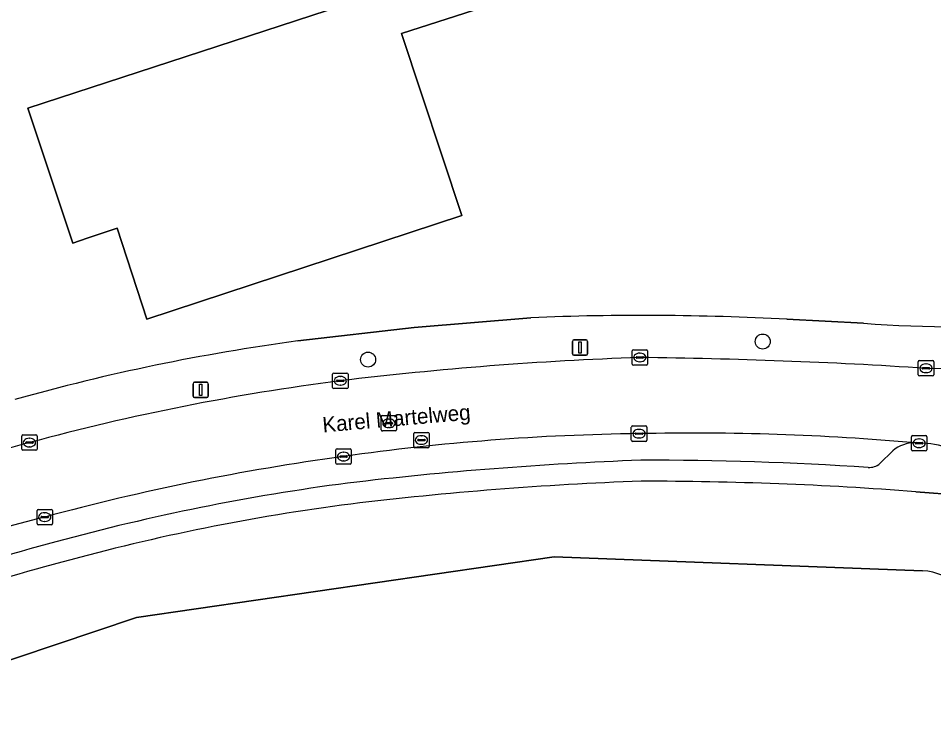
# Model space of a CAD drawing. Extents: x 159499 to 160349, y 382524 to 383273.
# Drawn here: x 159656.9 to 159716.4, y 382705.2 to 382752 of the extents above; entities that cross this region are included whole.
import ezdxf

# ---------------------------------------------------------------- set-up
doc = ezdxf.new("R2010")
doc.units = 0
for name, color, linetype in [('IMGEO_Boom', 7, 'Continuous'), ('IMGEO_Erf', 7, 'Continuous'), ('IMGEO_Kolk', 7, 'Continuous'), ('IMGEO_Lichtmast', 7, 'Continuous'), ('IMGEO_Openbare_ruimte_label', 7, 'Continuous'), ('IMGEO_Pand', 7, 'Continuous'), ('IMGEO_Parkeervlak_open', 7, 'Continuous'), ('IMGEO_Rijbaan_lokaal_open', 7, 'Continuous'), ('IMGEO_Rioolput', 7, 'Continuous'), ('IMGEO_Voetpad_open', 7, 'Continuous')]:
    doc.layers.add(name, color=color, linetype=linetype)

msp = doc.modelspace()

# ---------------------------------------------------------------- linework, layer by layer
at = {"layer": 'IMGEO_Boom'}
for centre in [(159705.309, 382730.985), (159679.639, 382729.808)]:
    msp.add_circle(centre, 0.489, dxfattribs=at)
at = {"layer": 'IMGEO_Erf'}
msp.add_lwpolyline([(159687.697, 382752.922), (159681.815, 382751.023), (159685.741, 382739.181), (159665.238, 382732.431), (159663.316, 382738.364), (159661.358, 382737.709), (159660.423, 382737.392), (159657.503, 382746.17), (159678.029, 382752.88), (159676.106, 382758.788), (159667.31, 382755.914), (159665.398, 382761.756), (159668.349, 382762.731), (159667.364, 382765.67), (159664.417, 382764.699), (159662.523, 382770.552), (159671.303, 382773.418), (159672.267, 382770.481), (159675.209, 382771.449), (159676.161, 382768.5), (159682.02, 382770.428), (159684.881, 382761.646)], close=True, dxfattribs=at)
for points in [[(159675.074, 382731.025), (159682.644, 382731.888), (159690.236, 382732.536)], [(159706.889, 382732.435), (159711.86, 382732.171)], [(159721.046, 382720.774), (159715.272, 382721.211)], [(159641.27, 382705.207), (159664.57, 382713.021), (159691.74, 382716.986), (159715.697, 382716.063)]]:
    msp.add_lwpolyline(points, dxfattribs=at)
for centre, radius, start, end in [((159697.488, 382555.269), 177.415, 86.96245, 92.34256), ((159718.869, 382831.635), 99.71, 265.96939, 273.05408), ((159693.42, 382596.018), 136.248, 97.73847, 105.65117), ((159705.287, 382500.203), 221.831, 92.03487, 96.93268), ((159697.556, 382491.794), 230.1, 85.58418, 90.03625), ((159696.201, 382584.04), 137.515, 97.39088, 105.38605), ((159693.098, 382590.157), 130.801, 104.78647, 112.89281), ((159715.545, 382712.325), 3.741, 45.57907, 87.6653)]:
    msp.add_arc(centre, radius, start, end, dxfattribs=at)
at = {"layer": 'IMGEO_Kolk'}
for p, q in [((159696.822, 382729.522), (159696.822, 382730.374)), ((159696.897, 382730.448), (159697.749, 382730.448)), ((159697.081, 382729.942), (159697.081, 382729.954)), ((159697.519, 382729.905), (159697.121, 382729.905)), ((159697.124, 382729.991), (159697.522, 382729.991)), ((159697.31, 382730.228), (159697.335, 382730.228)), ((159697.565, 382729.954), (159697.565, 382729.942)), ((159697.823, 382730.374), (159697.823, 382729.522)), ((159697.749, 382729.448), (159696.897, 382729.448)), ((159697.333, 382729.668), (159697.308, 382729.668)), ((159715.43, 382728.818), (159715.43, 382729.67)), ((159715.505, 382729.744), (159716.357, 382729.744)), ((159715.918, 382729.524), (159715.943, 382729.524)), ((159716.431, 382729.67), (159716.431, 382728.818)), ((159677.332, 382728.004), (159677.332, 382728.856)), ((159677.407, 382728.93), (159678.259, 382728.93)), ((159677.82, 382728.71), (159677.845, 382728.71)), ((159678.333, 382728.856), (159678.333, 382728.004)), ((159716.357, 382728.744), (159715.505, 382728.744)), ((159715.689, 382729.238), (159715.689, 382729.25)), ((159716.127, 382729.201), (159715.729, 382729.201)), ((159715.732, 382729.287), (159716.13, 382729.287)), ((159715.941, 382728.964), (159715.916, 382728.964)), ((159716.173, 382729.25), (159716.173, 382729.238)), ((159677.591, 382728.424), (159677.591, 382728.436)), ((159678.029, 382728.387), (159677.631, 382728.387)), ((159677.634, 382728.473), (159678.032, 382728.473)), ((159677.843, 382728.15), (159677.818, 382728.15)), ((159678.075, 382728.436), (159678.075, 382728.424)), ((159678.259, 382727.93), (159677.407, 382727.93)), ((159696.763, 382724.564), (159696.763, 382725.416)), ((159696.838, 382725.49), (159697.69, 382725.49)), ((159697.251, 382725.27), (159697.276, 382725.27)), ((159697.764, 382725.416), (159697.764, 382724.564)), ((159657.109, 382723.984), (159657.109, 382724.836)), ((159657.184, 382724.91), (159658.036, 382724.91)), ((159657.597, 382724.69), (159657.622, 382724.69)), ((159658.11, 382724.836), (159658.11, 382723.984)), ((159697.022, 382724.984), (159697.022, 382724.996)), ((159697.46, 382724.947), (159697.062, 382724.947)), ((159697.065, 382725.033), (159697.463, 382725.033)), ((159697.274, 382724.71), (159697.249, 382724.71)), ((159697.506, 382724.996), (159697.506, 382724.984)), ((159714.98, 382723.942), (159714.98, 382724.794)), ((159715.055, 382724.868), (159715.907, 382724.868)), ((159715.468, 382724.648), (159715.493, 382724.648)), ((159715.981, 382724.794), (159715.981, 382723.942)), ((159657.368, 382724.404), (159657.368, 382724.416)), ((159657.806, 382724.367), (159657.408, 382724.367)), ((159657.411, 382724.453), (159657.809, 382724.453)), ((159657.62, 382724.13), (159657.595, 382724.13)), ((159657.852, 382724.416), (159657.852, 382724.404)), ((159677.619, 382724.002), (159678.471, 382724.002)), ((159697.69, 382724.49), (159696.838, 382724.49)), ((159715.239, 382724.362), (159715.239, 382724.374)), ((159715.677, 382724.325), (159715.279, 382724.325)), ((159715.282, 382724.411), (159715.68, 382724.411)), ((159715.491, 382724.088), (159715.466, 382724.088)), ((159715.723, 382724.374), (159715.723, 382724.362)), ((159658.036, 382723.91), (159657.184, 382723.91)), ((159677.544, 382723.076), (159677.544, 382723.928)), ((159677.803, 382723.496), (159677.803, 382723.508)), ((159678.241, 382723.459), (159677.843, 382723.459)), ((159677.846, 382723.545), (159678.244, 382723.545)), ((159678.032, 382723.782), (159678.057, 382723.782)), ((159678.287, 382723.508), (159678.287, 382723.496)), ((159678.545, 382723.928), (159678.545, 382723.076)), ((159715.907, 382723.868), (159715.055, 382723.868)), ((159678.471, 382723.002), (159677.619, 382723.002)), ((159678.055, 382723.222), (159678.03, 382723.222)), ((159658.106, 382719.138), (159658.106, 382719.99)), ((159658.181, 382720.064), (159659.033, 382720.064)), ((159658.594, 382719.844), (159658.619, 382719.844)), ((159659.107, 382719.99), (159659.107, 382719.138)), ((159658.365, 382719.558), (159658.365, 382719.57)), ((159658.803, 382719.521), (159658.405, 382719.521)), ((159658.408, 382719.607), (159658.806, 382719.607)), ((159658.617, 382719.284), (159658.592, 382719.284)), ((159658.849, 382719.57), (159658.849, 382719.558)), ((159659.033, 382719.064), (159658.181, 382719.064))]:
    msp.add_line(p, q, dxfattribs=at)
for points in [[(159696.822, 382729.522), (159696.822, 382730.374)], [(159696.897, 382730.448), (159697.749, 382730.448)], [(159697.823, 382730.374), (159697.823, 382729.522)], [(159697.749, 382729.448), (159696.897, 382729.448)], [(159715.43, 382728.818), (159715.43, 382729.67)], [(159715.505, 382729.744), (159716.357, 382729.744)], [(159716.431, 382729.67), (159716.431, 382728.818)], [(159677.332, 382728.004), (159677.332, 382728.856)], [(159677.407, 382728.93), (159678.259, 382728.93)], [(159678.333, 382728.856), (159678.333, 382728.004)], [(159716.357, 382728.744), (159715.505, 382728.744)], [(159678.259, 382727.93), (159677.407, 382727.93)], [(159696.763, 382724.564), (159696.763, 382725.416)], [(159696.838, 382725.49), (159697.69, 382725.49)], [(159697.764, 382725.416), (159697.764, 382724.564)], [(159657.109, 382723.984), (159657.109, 382724.836)], [(159657.184, 382724.91), (159658.036, 382724.91)], [(159658.11, 382724.836), (159658.11, 382723.984)], [(159714.98, 382723.942), (159714.98, 382724.794)], [(159715.055, 382724.868), (159715.907, 382724.868)], [(159715.981, 382724.794), (159715.981, 382723.942)], [(159677.619, 382724.002), (159678.471, 382724.002)], [(159697.69, 382724.49), (159696.838, 382724.49)], [(159658.036, 382723.91), (159657.184, 382723.91)], [(159677.544, 382723.076), (159677.544, 382723.928)], [(159678.545, 382723.928), (159678.545, 382723.076)], [(159715.907, 382723.868), (159715.055, 382723.868)], [(159678.471, 382723.002), (159677.619, 382723.002)], [(159658.106, 382719.138), (159658.106, 382719.99)], [(159658.181, 382720.064), (159659.033, 382720.064)], [(159659.107, 382719.99), (159659.107, 382719.138)], [(159659.033, 382719.064), (159658.181, 382719.064)]]:
    msp.add_lwpolyline(points, dxfattribs=at)
for centre, radius, start, end in [((159696.899, 382730.372), 0.0765, 91.55205, 178.44795), ((159696.899, 382730.372), 0.0765, 91.55205, 178.44795), ((159697.121, 382729.951), 0.0403, 85.87752, 175.75265), ((159697.118, 382729.941), 0.0366, 178.93798, 274.71019), ((159697.522, 382729.948), 0.043, 264.86636, 352.45326), ((159697.526, 382729.953), 0.0386, 1.73085, 96.63898), ((159697.747, 382730.372), 0.0765, 1.55205, 88.44795), ((159697.747, 382730.372), 0.0765, 1.55205, 88.44795), ((159696.899, 382729.524), 0.0765, 181.55205, 268.44795), ((159696.899, 382729.524), 0.0765, 181.55205, 268.44795), ((159697.747, 382729.524), 0.0765, 271.55205, 358.44795), ((159697.747, 382729.524), 0.0765, 271.55205, 358.44795), ((159715.507, 382729.668), 0.0765, 91.55205, 178.44795), ((159715.507, 382729.668), 0.0765, 91.55205, 178.44795), ((159716.355, 382729.668), 0.0765, 1.55205, 88.44795), ((159716.355, 382729.668), 0.0765, 1.55205, 88.44795), ((159677.409, 382728.854), 0.0765, 91.55205, 178.44795), ((159677.409, 382728.854), 0.0765, 91.55205, 178.44795), ((159678.257, 382728.854), 0.0765, 1.55205, 88.44795), ((159678.257, 382728.854), 0.0765, 1.55205, 88.44795), ((159715.507, 382728.82), 0.0765, 181.55205, 268.44795), ((159715.507, 382728.82), 0.0765, 181.55205, 268.44795), ((159715.729, 382729.247), 0.0403, 85.87752, 175.75265), ((159715.726, 382729.237), 0.0366, 178.93798, 274.71019), ((159716.13, 382729.244), 0.043, 264.86636, 352.45326), ((159716.134, 382729.249), 0.0386, 1.73085, 96.63898), ((159716.355, 382728.82), 0.0765, 271.55205, 358.44795), ((159716.355, 382728.82), 0.0765, 271.55205, 358.44795), ((159677.631, 382728.433), 0.0403, 85.87752, 175.75265), ((159677.628, 382728.423), 0.0366, 178.93798, 274.71019), ((159678.032, 382728.43), 0.043, 264.86636, 352.45326), ((159678.036, 382728.435), 0.0386, 1.73085, 96.63898), ((159677.409, 382728.006), 0.0765, 181.55205, 268.44795), ((159677.409, 382728.006), 0.0765, 181.55205, 268.44795), ((159678.257, 382728.006), 0.0765, 271.55205, 358.44795), ((159678.257, 382728.006), 0.0765, 271.55205, 358.44795), ((159696.84, 382725.414), 0.0765, 91.55205, 178.44795), ((159696.84, 382725.414), 0.0765, 91.55205, 178.44795), ((159697.688, 382725.414), 0.0765, 1.55205, 88.44795), ((159697.688, 382725.414), 0.0765, 1.55205, 88.44795), ((159657.186, 382724.834), 0.0765, 91.55205, 178.44795), ((159657.186, 382724.834), 0.0765, 91.55205, 178.44795), ((159658.034, 382724.834), 0.0765, 1.55205, 88.44795), ((159658.034, 382724.834), 0.0765, 1.55205, 88.44795), ((159696.84, 382724.566), 0.0765, 181.55205, 268.44795), ((159696.84, 382724.566), 0.0765, 181.55205, 268.44795), ((159697.062, 382724.993), 0.0403, 85.87752, 175.75265), ((159697.059, 382724.983), 0.0366, 178.93798, 274.71019), ((159697.463, 382724.99), 0.043, 264.86636, 352.45326), ((159697.467, 382724.995), 0.0386, 1.73085, 96.63898), ((159697.688, 382724.566), 0.0765, 271.55205, 358.44795), ((159697.688, 382724.566), 0.0765, 271.55205, 358.44795), ((159715.057, 382724.792), 0.0765, 91.55205, 178.44795), ((159715.057, 382724.792), 0.0765, 91.55205, 178.44795), ((159715.905, 382724.792), 0.0765, 1.55205, 88.44795), ((159715.905, 382724.792), 0.0765, 1.55205, 88.44795), ((159657.186, 382723.986), 0.0765, 181.55205, 268.44795), ((159657.186, 382723.986), 0.0765, 181.55205, 268.44795), ((159657.408, 382724.413), 0.0403, 85.87752, 175.75265), ((159657.405, 382724.403), 0.0366, 178.93798, 274.71019), ((159657.809, 382724.41), 0.043, 264.86636, 352.45326), ((159657.813, 382724.415), 0.0386, 1.73085, 96.63898), ((159658.034, 382723.986), 0.0765, 271.55205, 358.44795), ((159658.034, 382723.986), 0.0765, 271.55205, 358.44795), ((159677.621, 382723.926), 0.0765, 91.55205, 178.44795), ((159677.621, 382723.926), 0.0765, 91.55205, 178.44795), ((159678.469, 382723.926), 0.0765, 1.55205, 88.44795), ((159678.469, 382723.926), 0.0765, 1.55205, 88.44795), ((159715.057, 382723.944), 0.0765, 181.55205, 268.44795), ((159715.057, 382723.944), 0.0765, 181.55205, 268.44795), ((159715.279, 382724.371), 0.0403, 85.87752, 175.75265), ((159715.276, 382724.361), 0.0366, 178.93798, 274.71019), ((159715.68, 382724.368), 0.043, 264.86636, 352.45326), ((159715.684, 382724.373), 0.0386, 1.73085, 96.63898), ((159715.905, 382723.944), 0.0765, 271.55205, 358.44795), ((159715.905, 382723.944), 0.0765, 271.55205, 358.44795), ((159677.843, 382723.505), 0.0403, 85.87752, 175.75265), ((159677.84, 382723.495), 0.0366, 178.93798, 274.71019), ((159678.244, 382723.502), 0.043, 264.86636, 352.45326), ((159678.248, 382723.507), 0.0386, 1.73085, 96.63898), ((159677.621, 382723.078), 0.0765, 181.55205, 268.44795), ((159677.621, 382723.078), 0.0765, 181.55205, 268.44795), ((159678.469, 382723.078), 0.0765, 271.55205, 358.44795), ((159678.469, 382723.078), 0.0765, 271.55205, 358.44795), ((159658.183, 382719.988), 0.0765, 91.55205, 178.44795), ((159658.183, 382719.988), 0.0765, 91.55205, 178.44795), ((159659.031, 382719.988), 0.0765, 1.55205, 88.44795), ((159659.031, 382719.988), 0.0765, 1.55205, 88.44795), ((159658.405, 382719.567), 0.0403, 85.87752, 175.75265), ((159658.402, 382719.557), 0.0366, 178.93798, 274.71019), ((159658.806, 382719.564), 0.043, 264.86636, 352.45326), ((159658.81, 382719.569), 0.0386, 1.73085, 96.63898), ((159658.183, 382719.14), 0.0765, 181.55205, 268.44795), ((159658.183, 382719.14), 0.0765, 181.55205, 268.44795), ((159659.031, 382719.14), 0.0765, 271.55205, 358.44795), ((159659.031, 382719.14), 0.0765, 271.55205, 358.44795)]:
    msp.add_arc(centre, radius, start, end, dxfattribs=at)
for centre, major_axis, ratio, start_param, end_param in [((159697.309, 382729.948), (-0.387, 0.002), 0.722429, 4.712389, 7.853982), ((159697.334, 382729.948), (-0.39, 0.002), 0.717154, 1.570796, 4.712389), ((159715.917, 382729.244), (-0.387, 0.002), 0.722429, 4.712389, 7.853982), ((159715.942, 382729.244), (-0.39, 0.002), 0.717154, 1.570796, 4.712389), ((159677.819, 382728.43), (-0.387, 0.002), 0.722429, 4.712389, 7.853982), ((159677.844, 382728.43), (-0.39, 0.002), 0.717154, 1.570796, 4.712389), ((159697.25, 382724.99), (-0.387, 0.002), 0.722429, 4.712389, 7.853982), ((159697.275, 382724.99), (-0.39, 0.002), 0.717154, 1.570796, 4.712389), ((159657.596, 382724.41), (-0.387, 0.002), 0.722429, 4.712389, 7.853982), ((159657.621, 382724.41), (-0.39, 0.002), 0.717154, 1.570796, 4.712389), ((159715.467, 382724.368), (-0.387, 0.002), 0.722429, 4.712389, 7.853982), ((159715.492, 382724.368), (-0.39, 0.002), 0.717154, 1.570796, 4.712389), ((159678.031, 382723.502), (-0.387, 0.002), 0.722429, 4.712389, 7.853982), ((159678.056, 382723.502), (-0.39, 0.002), 0.717154, 1.570796, 4.712389), ((159658.593, 382719.564), (-0.387, 0.002), 0.722429, 4.712389, 7.853982), ((159658.618, 382719.564), (-0.39, 0.002), 0.717154, 1.570796, 4.712389)]:
    msp.add_ellipse(centre, major_axis=major_axis, ratio=ratio, start_param=start_param, end_param=end_param, dxfattribs=at)
at = {"layer": 'IMGEO_Lichtmast'}
for p, q in [((159693.032, 382731.095), (159693.822, 382731.095)), ((159693.822, 382731.095), (159693.032, 382731.095)), ((159692.932, 382730.195), (159692.932, 382730.995)), ((159692.932, 382730.995), (159692.932, 382730.195)), ((159693.922, 382730.995), (159693.922, 382730.195)), ((159693.922, 382730.195), (159693.922, 382730.995)), ((159693.822, 382730.095), (159693.032, 382730.095)), ((159693.032, 382730.095), (159693.822, 382730.095)), ((159668.254, 382727.439), (159668.254, 382728.239)), ((159668.254, 382728.239), (159668.254, 382727.439)), ((159668.354, 382728.339), (159669.144, 382728.339)), ((159669.144, 382728.339), (159668.354, 382728.339)), ((159669.244, 382728.239), (159669.244, 382727.439)), ((159669.244, 382727.439), (159669.244, 382728.239)), ((159669.144, 382727.339), (159668.354, 382727.339)), ((159668.354, 382727.339), (159669.144, 382727.339))]:
    msp.add_line(p, q, dxfattribs=at)
for points in [[(159693.352, 382730.97), (159693.502, 382730.97), (159693.502, 382730.22), (159693.352, 382730.22), (159693.352, 382730.97)], [(159668.674, 382728.214), (159668.824, 382728.214), (159668.824, 382727.464), (159668.674, 382727.464), (159668.674, 382728.214)]]:
    msp.add_lwpolyline(points, dxfattribs=at)
for centre, start, end in [((159693.032, 382730.995), 90, 180), ((159693.032, 382730.995), 90, 180), ((159693.822, 382730.995), 0, 90), ((159693.822, 382730.995), 360, 90), ((159693.032, 382730.195), 180, 270), ((159693.032, 382730.195), 180, 270), ((159693.822, 382730.195), 270, 0), ((159693.822, 382730.195), 270, 0), ((159668.354, 382728.239), 90, 180), ((159668.354, 382728.239), 90, 180), ((159669.144, 382728.239), 0, 90), ((159669.144, 382728.239), 360, 90), ((159668.354, 382727.439), 180, 270), ((159668.354, 382727.439), 180, 270), ((159669.144, 382727.439), 270, 0), ((159669.144, 382727.439), 270, 0)]:
    msp.add_arc(centre, 0.1, start, end, dxfattribs=at)
at = {"layer": 'IMGEO_Pand'}
msp.add_lwpolyline([(159681.815, 382751.023), (159687.697, 382752.922), (159684.881, 382761.646), (159682.02, 382770.428), (159676.161, 382768.5), (159675.209, 382771.449), (159672.267, 382770.481), (159671.303, 382773.418), (159662.523, 382770.552), (159664.417, 382764.699), (159667.364, 382765.67), (159668.349, 382762.731), (159665.398, 382761.756), (159667.31, 382755.914), (159676.106, 382758.788), (159678.029, 382752.88), (159657.503, 382746.17), (159660.423, 382737.392), (159661.358, 382737.709), (159663.316, 382738.364), (159665.238, 382732.431), (159685.741, 382739.181)], close=True, dxfattribs=at)
msp.add_lwpolyline([(159715.697, 382716.063), (159691.74, 382716.986), (159664.57, 382713.021), (159641.27, 382705.207)], dxfattribs=at)
msp.add_arc((159715.545, 382712.325), 3.741, 45.57907, 87.6653, dxfattribs=at)
at = {"layer": 'IMGEO_Parkeervlak_open'}
msp.add_lwpolyline([(159712.935, 382723.041), (159713.775, 382723.875)], dxfattribs=at)
for centre, radius, start, end in [((159699.017, 382577.567), 147.434, 90.68145, 98.17842), ((159700.776, 382560.643), 164.385, 84.95233, 91.22406), ((159715.173, 382722.245), 2.147, 88.22757, 130.60336), ((159698.899, 382570.59), 154.328, 97.76654, 105.13436), ((159706.243, 382487.021), 236.406, 92.14832, 96.786), ((159697.786, 382501.576), 221.685, 86.27886, 90.1048), ((159712.228, 382723.925), 1.132, 267.28454, 308.67952), ((159696.794, 382580.988), 141.992, 97.48028, 105.29974), ((159685.275, 382613.183), 109.673, 104.07275, 113.85158), ((159694.437, 382586.106), 136.436, 104.91228, 112.74508)]:
    msp.add_arc(centre, radius, start, end, dxfattribs=at)
at = {"layer": 'IMGEO_Rijbaan_lokaal_open'}
msp.add_lwpolyline([(159715.239, 382724.391), (159715.36, 382724.383), (159715.481, 382724.369)], dxfattribs=at)
for centre, radius, start, end in [((159718.609, 382887.14), 157.921, 269.02843, 287.72025), ((159705.491, 382499.343), 230.749, 92.02869, 96.88426), ((159693.353, 382379.227), 350.742, 86.30914, 89.35141), ((159697.26, 382577.785), 151.89, 97.34835, 105.132), ((159699.017, 382577.567), 147.434, 90.68145, 98.17842), ((159700.776, 382560.643), 164.385, 84.95233, 91.22406), ((159692.261, 382592.582), 136.305, 104.72718, 113.3317), ((159715.467, 382718.252), 6.117, 52.08751, 89.87165), ((159698.899, 382570.59), 154.328, 97.76654, 105.13436), ((159685.275, 382613.183), 109.673, 104.07275, 113.85158)]:
    msp.add_arc(centre, radius, start, end, dxfattribs=at)
at = {"layer": 'IMGEO_Rioolput'}
for p, q in [((159680.491, 382725.238), (159680.491, 382726.09)), ((159680.566, 382726.164), (159681.418, 382726.164)), ((159680.979, 382725.944), (159681.004, 382725.944)), ((159681.492, 382726.09), (159681.492, 382725.238)), ((159681.418, 382725.164), (159680.566, 382725.164)), ((159680.75, 382725.658), (159680.75, 382725.67)), ((159681.188, 382725.621), (159680.79, 382725.621)), ((159680.793, 382725.707), (159681.191, 382725.707)), ((159681.002, 382725.384), (159680.977, 382725.384)), ((159681.234, 382725.67), (159681.234, 382725.658)), ((159682.608, 382724.15), (159682.608, 382725.002)), ((159682.683, 382725.076), (159683.535, 382725.076)), ((159682.867, 382724.57), (159682.867, 382724.582)), ((159683.305, 382724.533), (159682.907, 382724.533)), ((159682.91, 382724.619), (159683.308, 382724.619)), ((159683.096, 382724.856), (159683.121, 382724.856)), ((159683.351, 382724.582), (159683.351, 382724.57)), ((159683.609, 382725.002), (159683.609, 382724.15)), ((159683.535, 382724.076), (159682.683, 382724.076)), ((159683.119, 382724.296), (159683.094, 382724.296))]:
    msp.add_line(p, q, dxfattribs=at)
for points in [[(159680.491, 382725.238), (159680.491, 382726.09)], [(159680.566, 382726.164), (159681.418, 382726.164)], [(159681.492, 382726.09), (159681.492, 382725.238)], [(159681.418, 382725.164), (159680.566, 382725.164)], [(159682.608, 382724.15), (159682.608, 382725.002)], [(159682.683, 382725.076), (159683.535, 382725.076)], [(159683.609, 382725.002), (159683.609, 382724.15)], [(159683.535, 382724.076), (159682.683, 382724.076)]]:
    msp.add_lwpolyline(points, dxfattribs=at)
for centre, radius, start, end in [((159680.568, 382726.088), 0.0765, 91.55205, 178.44795), ((159680.568, 382726.088), 0.0765, 91.55205, 178.44795), ((159681.416, 382726.088), 0.0765, 1.55205, 88.44795), ((159681.416, 382726.088), 0.0765, 1.55205, 88.44795), ((159680.568, 382725.24), 0.0765, 181.55205, 268.44795), ((159680.568, 382725.24), 0.0765, 181.55205, 268.44795), ((159680.79, 382725.667), 0.0403, 85.87752, 175.75265), ((159680.787, 382725.657), 0.0366, 178.93798, 274.71019), ((159681.191, 382725.664), 0.043, 264.86636, 352.45326), ((159681.195, 382725.669), 0.0386, 1.73085, 96.63898), ((159681.416, 382725.24), 0.0765, 271.55205, 358.44795), ((159681.416, 382725.24), 0.0765, 271.55205, 358.44795), ((159682.685, 382725), 0.0765, 91.55205, 178.44795), ((159682.685, 382725), 0.0765, 91.55205, 178.44795), ((159682.907, 382724.579), 0.0403, 85.87752, 175.75265), ((159682.904, 382724.569), 0.0366, 178.93798, 274.71019), ((159683.308, 382724.576), 0.043, 264.86636, 352.45326), ((159683.312, 382724.581), 0.0386, 1.73085, 96.63898), ((159683.533, 382725), 0.0765, 1.55205, 88.44795), ((159683.533, 382725), 0.0765, 1.55205, 88.44795), ((159682.685, 382724.152), 0.0765, 181.55205, 268.44795), ((159682.685, 382724.152), 0.0765, 181.55205, 268.44795), ((159683.533, 382724.152), 0.0765, 271.55205, 358.44795), ((159683.533, 382724.152), 0.0765, 271.55205, 358.44795)]:
    msp.add_arc(centre, radius, start, end, dxfattribs=at)
for centre, major_axis, ratio, start_param, end_param in [((159680.978, 382725.664), (-0.387, 0.002), 0.722429, 4.712389, 7.853982), ((159681.003, 382725.664), (-0.39, 0.002), 0.717154, 1.570796, 4.712389), ((159683.095, 382724.576), (-0.387, 0.002), 0.722429, 4.712389, 7.853982), ((159683.12, 382724.576), (-0.39, 0.002), 0.717154, 1.570796, 4.712389)]:
    msp.add_ellipse(centre, major_axis=major_axis, ratio=ratio, start_param=start_param, end_param=end_param, dxfattribs=at)
at = {"layer": 'IMGEO_Voetpad_open'}
for points in [[(159690.236, 382732.536), (159682.644, 382731.888), (159675.074, 382731.025)], [(159711.86, 382732.171), (159706.889, 382732.435)], [(159715.481, 382724.369), (159715.36, 382724.383), (159715.239, 382724.391)], [(159713.775, 382723.875), (159712.935, 382723.041)], [(159715.272, 382721.211), (159721.046, 382720.774)]]:
    msp.add_lwpolyline(points, dxfattribs=at)
for centre, radius, start, end in [((159718.609, 382887.14), 157.921, 269.02843, 287.72025), ((159697.488, 382555.269), 177.415, 86.96245, 92.34256), ((159718.869, 382831.635), 99.71, 265.96939, 273.05408), ((159693.42, 382596.018), 136.248, 97.73847, 105.65117), ((159705.491, 382499.343), 230.749, 92.02869, 96.88426), ((159693.353, 382379.227), 350.742, 86.30914, 89.35141), ((159697.26, 382577.785), 151.89, 97.34835, 105.132), ((159692.261, 382592.582), 136.305, 104.72718, 113.3317), ((159715.173, 382722.245), 2.147, 88.22757, 130.60336), ((159715.467, 382718.252), 6.117, 52.08751, 89.87165), ((159706.243, 382487.021), 236.406, 92.14832, 96.786), ((159697.786, 382501.576), 221.685, 86.27886, 90.1048), ((159712.228, 382723.925), 1.132, 267.28454, 308.67952), ((159696.794, 382580.988), 141.992, 97.48028, 105.29974), ((159705.287, 382500.203), 221.831, 92.03487, 96.93268), ((159697.556, 382491.794), 230.1, 85.58418, 90.03625), ((159696.201, 382584.04), 137.515, 97.39088, 105.38605), ((159694.437, 382586.106), 136.436, 104.91228, 112.74508), ((159693.098, 382590.157), 130.801, 104.78647, 112.89281)]:
    msp.add_arc(centre, radius, start, end, dxfattribs=at)

# ---------------------------------------------------------------- texts
at = {"layer": 'IMGEO_Openbare_ruimte_label'}
msp.add_text('Karel Martelweg', height=1, rotation=4.99208, dxfattribs=at).set_placement((159676.712, 382725.067))

doc.saveas('drawing.dxf')
